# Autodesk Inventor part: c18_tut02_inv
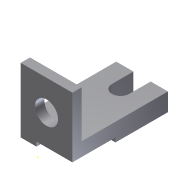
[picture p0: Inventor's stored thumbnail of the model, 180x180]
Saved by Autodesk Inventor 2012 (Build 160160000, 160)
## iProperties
Created: 2010-02
Part Number: c18_tut02_inv
Document SubType Name: Modeling
Designer: CADSoft
Density: 1 g/cm^3
Material: Default
Author: CADSoft
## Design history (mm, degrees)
sketch "Sketch1"
  geometry: 1 further point
sketch "Sketch2"
  geometry: L1 (0, 90)-(0, 0); L2 (0, 0)-(145, 0); L3 (145, 0)-(145, 25); L4 (145, 25)-(25, 25); L5 (25, 25)-(25, 90); L6 (25, 90)-(0, 90); 1 further point
  constraints: 12 end point, 1 coincident, 1 perpendicular, 1 other
  dimensions: "d0" = 90 distance of L1.start L1.end; "d1" = 25 distance of L5.end L1.start; "d2" = 145 distance of L1.end L2.end
extrude "Extrusion1" new body sketch "Sketch2" stored distance "d3" = 72; taper "d4" = 0 deg
sketch "Sketch3"
  geometry: L1 (0, 0)-(-6, -0.015); L2 (-6, -0.015)-(-6, 71.985); L3 (-6, 71.985)-(0, 72); L4 (0, 72)-(0, 0); L5 (0, 145)-(0, 0) reference
  constraints: 8 end point, 1 coincident, 1 point on line
  dimensions: "d5" = 72 distance of L3.end L1.start; "d6" = 6 distance of L1.start L1.end
extrude "Extrusion2" cut sketch "Sketch3" distance "d7" = 50; taper "d8" = 0 deg
sketch "Sketch4"
  geometry: L1 (72, -24)-(72, -60); L2 (0, -60)-(0, -24); L3 (0, -90)-(22, -90) reference; L4 (0, 0)-(0, -90) reference; L5 (72, -84)-(72, 0) reference; L6 (0, -24)-(12, -24); L7 (60, -24)-(72, -24); L8 (72, -60)-(60, -60); L9 (12, -60)-(0, -60); A1 r 30 centre (36, -42) between (12, -60) and (60, -60); A2 r 30 centre (36, -42) between (60, -24) and (12, -24)
  constraints: 12 end point, 4 point on circle, 2 centre point, 2 collinear, 1 concentric
  dimensions: "d10" = 48 distance from line of L3 A1.centre; "d11" = 36 distance from line of L4 A1.centre; "d14" = 30 radius of A2; "d15" = 36 distance of L2.start L2.end
extrude "Extrusion3" cut sketch "Sketch4" distance "d16" = 12; taper "d17" = 0 deg
sketch "Sketch5"
  geometry: C1 r 12 at (36, -42); A1 r 30 centre (36, -42) between (60, -24) and (12, -24) reference; 1 further point
  constraints: 1 centre point, 1 coincident
  dimensions: "d18" = 24 diameter of C1
extrude "Extrusion4" cut sketch "Sketch5" stored distance "d19" = 12; taper "d20" = 0 deg
sketch "Sketch6"
  geometry: L1 (24, 0)-(24, -50); L2 (48, -50)-(48, 0); L3 (48, 0)-(24, 0); L4 (72, 0)-(0, 0) reference; L5 (72, -120)-(72, 0) reference; A1 r 12 centre (36, -50) between (24, -50) and (48, -50); 1 further point
  constraints: 6 end point, 2 point on circle, 2 tangent, 2 vertical, 1 centre point, 1 collinear, 1 horizontal
  dimensions: "d21" = 50 distance of L2.start L2.end; "d22" = 12 radius of A1; "d23" = 36 distance from line of L5 A1.centre
extrude "Extrusion5" cut sketch "Sketch6" stored distance "d24" = 12; taper "d25" = 0 deg
feature "Alias Freeform1"
body "Solid1"
